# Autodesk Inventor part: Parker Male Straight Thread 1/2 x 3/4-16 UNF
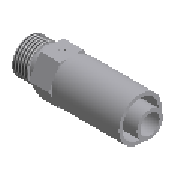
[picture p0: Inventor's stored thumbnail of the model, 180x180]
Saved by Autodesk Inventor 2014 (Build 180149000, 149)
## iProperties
IsCustomPart: 0
Company: Parker Hannifin
Created: 2008-02
Part Number: Parker Male Straight Thread 1/2 x 3/4-16 UNF
Material: Steel
Description: Parker Fitting
Document SubType Name: Modeling
Standard: Parker
Designer: floress
Manufacturer: Parker
Language: en-US
Size Designation: 1/2 x 3/4-16 UNF
Categories: <MemberInstance><Categories><Category DisplayName="Tube &amp; Pipe" InternalName="4347fa0f-2144-441d-94cd-e3e15c92b736" Mnemonic="TUBEANDPIPE"><CategoryParamete
Density: 7.85 g/cm^3
Mass: 110.637 g
Surface Area: 116.249 cm^2
Volume: 14.0938 cm^3
Appearance: Metal-Steel
NAME: PIPING: Parker Male Straight Thread
DATA: <meta><inlinegroups number="1" deflen="7.0358"></inlinegroups><connections number="2"></connections><angles><a>3.14159265358979</a></angles></meta>
Author: floress
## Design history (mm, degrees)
sketch "Sketch1"
  geometry: L1 (0, 13.59)-(0, 3.51) reference; L2 (-14.176, 0)-(85.056, 0) reference; L3 (0, 4.95)-(0, 9.525); L4 (0, 9.525)-(8.6, 9.525); L5 (8.6, 9.525)-(8.6, 8.579); L6 (8.6, 8.579)-(10.725, 8.579); L7 (10.725, 8.579)-(10.725, 11.113); L8 (10.725, 11.113)-(23.984, 11.113); L9 (23.984, 11.113)-(23.984, 11.5); L10 (23.984, 11.5)-(27.784, 11.5); L11 (27.784, 11.5)-(27.784, 12.15); L12 (27.784, 12.15)-(62.484, 12.15); L13 (62.484, 12.15)-(62.484, 11.25); L14 (62.484, 11.25)-(35.18, 11.25); L15 (35.18, 11.25)-(35.18, 10.05); L16 (35.18, 10.05)-(30.48, 10.05); L17 (30.48, 10.05)-(30.48, 6.65); L18 (30.48, 6.65)-(70.88, 6.65); L19 (70.88, 6.65)-(70.88, 4.95); L20 (70.88, 4.95)-(0, 4.95)
  constraints: 36 end point, 14 parallel, 3 perpendicular, 1 point on line
  dimensions: "d0" = 9.9 diameter of L20 L2 (= HOLE); "d1" = 13.3 diameter of L18 L2 (= P1); "d2" = 20.1 diameter of L16 L2 (= U1); "d3" = 22.5 diameter of L14 L2 (= V1); "d4" = 24.3 diameter of L12 L2 (= SHELL_CRIMP); "d5" = 62.484 distance between parallel lines of L13 L1 (= A1); "d6" = 13.2588 distance between parallel lines of L7 L9 (= F1); "d7" = 23 diameter of L10 L2 (= O1); "d8" = 22.225 diameter of L8 L2 (= H1); "d9" = 40.4 distance between parallel lines of L17 L19 (= W1); "d10" = 4.7 distance between parallel lines of L15 L17 (= S1 - T1); "d11" = 38.5 distance between parallel lines of L9 L13 (= R1); "d12" = 3.8 distance between parallel lines of L11 L9 (= T1); "d13" = 30.48 distance between parallel lines of L17 L1 (= B1); "d14" = 19.05 diameter of L4 L2 (= Mt); "d15" = 17.1577 diameter of L6 L2 (= MD); "d16" = 8.6 distance between parallel lines of L5 L3 (= Lt)
revolve "Revolution1" sketch "Sketch1" stored, may be unused: angle "d21" = 90 deg
sketch "Sketch2"
  geometry: L1 (6.416, 11.113)-(12.832, 0); L2 (12.832, 0)-(6.416, -11.112); L3 (6.416, -11.112)-(-6.416, -11.113); L4 (-6.416, -11.113)-(-12.832, 0); L5 (-12.832, 0)-(-6.416, 11.112); L6 (-6.416, 11.112)-(6.416, 11.113); C1 r 8.579 at (0, 0) reference; 4 further points
  constraints: 12 end point, 2 coincident, 2 vertical alignment, 1 horizontal, 1 midpoint, 14 other
extrude "Extrusion1" join sketch "Sketch2" distance "d17" = 13.2588 (= F1); taper "d18" = 0 deg
thread "Thread1" dims "d24" = 25.4, "d25" = 0
sketch "Sketch3"
  geometry: L1 (0, 12.832)-(0, 0) reference; L2 (-24.901, 6.416)-(74.331, 6.416) reference; L3 (5.529, 7.516)-(6.929, 7.516); L4 (7.529, 6.916)-(7.529, 5.916); L5 (6.929, 5.316)-(5.829, 5.316); L6 (5.529, 5.016)-(5.529, 4.316); L7 (5.829, 4.316)-(5.829, 5.016); L8 (5.829, 5.016)-(6.929, 5.016); L9 (7.829, 5.916)-(7.829, 6.916); L10 (6.929, 7.816)-(5.529, 7.816); L11 (5.529, 7.816)-(5.529, 7.516); L12 (5.529, 4.316)-(5.829, 4.316); L13 (6.629, 6.716)-(4.329, 6.716); L14 (4.329, 6.716)-(4.329, 6.416); L15 (4.329, 6.416)-(6.629, 6.416); L16 (6.629, 6.416)-(6.629, 6.716); A1 r 0.6 centre (6.929, 6.916) between (7.529, 6.916) and (6.929, 7.516); A2 r 0.3 centre (5.829, 5.016) between (5.829, 5.316) and (5.529, 5.016); A3 r 0.6 centre (6.929, 5.916) between (6.929, 5.316) and (7.529, 5.916); A4 r 0.9 centre (6.929, 5.916) between (6.929, 5.016) and (7.829, 5.916); A5 r 0.9 centre (6.929, 6.916) between (7.829, 6.916) and (6.929, 7.816); 1 further point
  constraints: 28 end point, 10 point on circle, 7 parallel, 6 tangent, 5 centre point, 5 perpendicular, 1 equal radius, 1 horizontal, 1 midpoint, 1 point on line, 10 other
  dimensions: "d19" = 0.6 radius of A1 (= L_G); "d20" = 0.3 radius of A2 (= L_H); "d22" = 0.3 distance between parallel lines of L7 L6 (= L_H); "d23" = 2 distance between parallel lines of L11 L4 (= L_E); "d26" = 2 distance between parallel lines of L6 L4 (= L_E); "d27" = 2.2 distance between parallel lines of L5 L3 (= L_B); "d28" = 3.2 distance between parallel lines of L12 L3 (= L_A); "d29" = 0.3 distance between parallel lines of L15 L13 (= L_H); "d30" = 0.9 distance between parallel lines of L16 L4 (= L_F); "d31" = 3.2 distance between parallel lines of L14 L4 (= L_D); "d32" = 1.1 distance between parallel lines of L15 L3 (= L_C); "d33" = 6.6294 distance between parallel lines of L16 L1 (= 0.5 x F1)
emboss "Emboss2" sketch "Sketch3" dims "d47" = 0.2, "d108" = 0
workaxis "Work Axis1"
workpoint "Work Point1"
workaxis "Work Axis2"
workpoint "Work Point2"
workaxis "Work Axis3"
workaxis "Work Axis4"
workpoint "Work Point3"
workpoint "Work Point4"
body "Solid1"
emboss "Emboss1" sketch "Sketch3" dims "d34" = 0.2, "d94" = 0
sketch "Sketch4"
  geometry: L1 (0, 12.832)-(0, 0) reference; L2 (13.259, 0)-(13.259, 3.456) reference; L3 (7.729, 5.316)-(6.329, 5.316); L4 (5.729, 5.916)-(5.729, 6.916); L5 (6.329, 7.516)-(7.429, 7.516); L6 (7.729, 7.816)-(7.729, 8.516); L7 (7.429, 8.516)-(7.429, 7.816); L8 (7.429, 7.816)-(6.329, 7.816); L9 (5.429, 6.916)-(5.429, 5.916); L10 (6.329, 5.016)-(7.729, 5.016); L11 (7.729, 5.316)-(7.729, 5.016); L12 (7.729, 8.516)-(7.429, 8.516); L13 (6.629, 6.116)-(8.929, 6.116); L14 (8.929, 6.116)-(8.929, 6.416); L15 (8.929, 6.416)-(6.629, 6.416); L16 (6.629, 6.416)-(6.629, 6.116); L17 (74.331, 6.416)-(-24.901, 6.416) reference; A1 r 0.6 centre (6.329, 5.916) between (5.729, 5.916) and (6.329, 5.316); A2 r 0.6 centre (6.329, 6.916) between (6.329, 7.516) and (5.729, 6.916); A3 r 0.3 centre (7.429, 7.816) between (7.429, 7.516) and (7.729, 7.816); A4 r 0.9 centre (6.329, 6.916) between (6.329, 7.816) and (5.429, 6.916); A5 r 0.9 centre (6.329, 5.916) between (5.429, 5.916) and (6.329, 5.016); 1 further point
  constraints: 28 end point, 10 point on circle, 6 parallel, 6 perpendicular, 6 tangent, 5 centre point, 1 equal radius, 1 horizontal, 1 midpoint, 1 point on line, 10 other
  dimensions: "d35" = 0.6 radius of A1 (= L_G); "d36" = 0.3 radius of A3 (= L_H); "d37" = 0.3 distance between parallel lines of L6 L7 (= L_H); "d38" = 2.2 distance between parallel lines of L5 L3 (= L_B); "d39" = 3.2 distance between parallel lines of L12 L3 (= L_A); "d40" = 2 distance between parallel lines of L11 L4 (= L_E); "d41" = 2 distance between parallel lines of L6 L4 (= L_E); "d42" = 0.3 distance between parallel lines of L15 L13 (= L_H); "d43" = 0.9 distance between parallel lines of L16 L4 (= L_F); "d44" = 3.2 distance between parallel lines of L14 L4 (= L_D); "d45" = 1.1 distance between parallel lines of L15 L3 (= L_C); "d46" = 6.6294 distance between parallel lines of L16 L1 (= 0.5 x F1)
other parameters: "A1" = 62.484 [user parameter; used in 1 equation term], "B1" = 30.48 [user parameter; used in 1 equation term], "H1" = 22.225 [user parameter; used in 1 equation term], "F1" = 13.2588 [user parameter; used in 4 equation terms], "Mt" = 19.05 [user parameter; used in 1 equation term], "Lt" = 8.6 [user parameter; used in 1 equation term], "MD" = 17.1577 [user parameter; used in 1 equation term], "O1" = 23 [user parameter; used in 1 equation term], "P1" = 13.3 [user parameter; used in 1 equation term], "R1" = 38.5 [user parameter; used in 1 equation term], "S1" = 8.5 [user parameter; used in 1 equation term], "T1" = 3.8 [user parameter; used in 2 equation terms], "U1" = 20.1 [user parameter; used in 1 equation term], "V1" = 22.5 [user parameter; used in 1 equation term], "W1" = 40.4 [user parameter; used in 1 equation term], "HOLE" = 9.9 [user parameter; used in 1 equation term], "SHELL_CRIMP" = 24.3 [user parameter; used in 1 equation term], "L_A" = 3.2 [user parameter; used in 2 equation terms], "L_B" = 2.2 [user parameter; used in 2 equation terms], "L_C" = 1.1 [user parameter; used in 2 equation terms], "L_D" = 3.2 [user parameter; used in 2 equation terms], "L_E" = 2 [user parameter; used in 4 equation terms], "L_F" = 0.9 [user parameter; used in 2 equation terms], "L_G" = 0.6 [user parameter; used in 2 equation terms], "L_H" = 0.3 [user parameter; used in 6 equation terms], "Size_Designation" = 12.345 [user parameter]
